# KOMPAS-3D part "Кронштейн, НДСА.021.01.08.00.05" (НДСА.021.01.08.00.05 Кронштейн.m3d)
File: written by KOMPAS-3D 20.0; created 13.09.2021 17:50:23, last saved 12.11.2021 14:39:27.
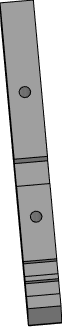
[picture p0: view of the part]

Document properties: Полное имя файла: C:\Users\korychko\Desktop\PLM\НДСА.021.01.08.00.05 Кронштейн.m3d

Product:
- Part/product: Кронштейн  | designation НДСА.021.01.08.00.05
    Материал: Д16  ГОСТ 4784-2019 (density 2800 kg/m3)
    Масса: 0.138473
    additional columns: <item xmlns="http://appius.ru/pdm" xmlns:xs="http://www.w3.org/2001/XMLSchema" x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; <item xmlns="http://appius.ru/pdm" xmlns:xs="http://www.w3.org/2001/XMLSchema" x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; <item xmlns="http://appius.ru/pdm" xmlns:xs="http://www.w3.org/2001/XMLSchema" x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
    source file: НДСА.021.01.08.00.05 Кронштейн.cdw

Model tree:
1. Эскиз:1
2. Элемент выдавливания:1
     Расстояние 1 = 135
3. Эскиз:2  (with: Элемент выдавливания:1)
4. Элемент выдавливания:2
5. Смещенная плоскость:1
     Расстояние = -5.75
6. Сечение:1
7. Эскиз:3  (with: Сечение:1)
8. Эскиз:4  (with: Элемент выдавливания:1, Сечение:1)
9. Эскиз:5  (with: Элемент выдавливания:1)
10. Элемент выдавливания:5
11. Отверстие:2  (with: Элемент выдавливания:1, Сечение:1)  (labels: M6)
     Глубина выреза = 15; Диаметр отверстия = 4.91747; Угол конуса дна = 118; Расстояние 1 = 13.75; Расстояние 2 = 7
12. M6  (with: Элемент выдавливания:1)  (labels: M6; cil0_24705-2004 coarse)
     Длина резьбы = 10; Шаг резьбы = 1; Номинальный диаметр резьбы = 6
13. Отверстие:3  (with: Сечение:1, M6)  (labels: M6; cil0_24705-2004 coarse)
     Глубина выреза = 15; Диаметр отверстия = 4.91747; Угол конуса дна = 118; Расстояние 1 = 7; Расстояние 2 = 40; Длина резьбы = 10; Шаг резьбы = 1; Номинальный диаметр резьбы = 6
14. Отверстие:4  (with: Сечение:1, M6)  (labels: M6; cil0_24705-2004 coarse)
     Глубина выреза = 15; Диаметр отверстия = 4.91747; Угол конуса дна = 118; Расстояние 1 = 95; Расстояние 2 = 7; Длина резьбы = 10; Шаг резьбы = 1; Номинальный диаметр резьбы = 6
15. Скругление:1  (with: Элемент выдавливания:1)  (labels: Д16  ГОСТ 4784-2019)
     Радиус = 5

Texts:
  НДСА.021.01.08.00.05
